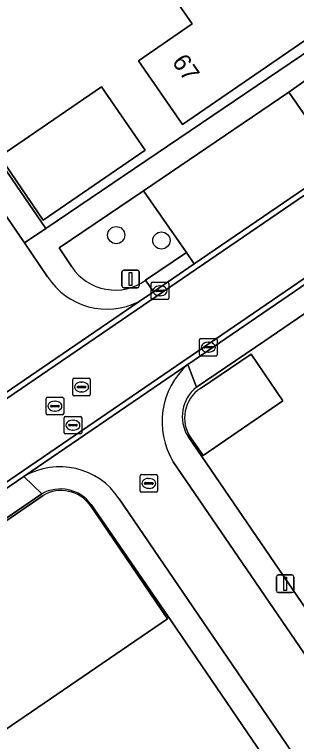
# Model space of a CAD drawing. Extents: x 155275 to 156265, y 382654 to 383635.
# Drawn here: x 155684.01 to 155700.06, y 383313.6 to 383354.97 of the extents above; entities that cross this region are included whole.
import ezdxf

# ---------------------------------------------------------------- set-up
doc = ezdxf.new("R2010")
doc.units = 0
for name, color, linetype in [('IMGEO_Boom', 7, 'Continuous'), ('IMGEO_Erf', 7, 'Continuous'), ('IMGEO_Groenvoorziening', 7, 'Continuous'), ('IMGEO_Kolk', 7, 'Continuous'), ('IMGEO_Lichtmast', 7, 'Continuous'), ('IMGEO_Pand', 7, 'Continuous'), ('IMGEO_Pand_nummerreeks', 7, 'Continuous'), ('IMGEO_Parkeervlak_open', 7, 'Continuous'), ('IMGEO_Rijbaan_lokaal_gesloten', 7, 'Continuous'), ('IMGEO_Rijbaan_lokaal_open', 7, 'Continuous'), ('IMGEO_Rioolput', 7, 'Continuous'), ('IMGEO_Voetpad_open', 7, 'Continuous')]:
    doc.layers.add(name, color=color, linetype=linetype)

msp = doc.modelspace()

# ---------------------------------------------------------------- linework, layer by layer
at = {"layer": 'IMGEO_Boom'}
for centre in [(155689.797, 383342.417), (155692.37, 383342.11)]:
    msp.add_circle(centre, 0.489, dxfattribs=at)
at = {"layer": 'IMGEO_Erf'}
for points in [[(155657.299, 383431.777), (155657.022, 383432.185), (155634.905, 383417.186), (155657.35, 383384.321), (155685.798, 383342.799), (155707.917, 383357.778), (155706.87, 383359.32)], [(155701.527, 383364.294), (155705.591, 383358.305), (155702.158, 383355.941), (155702.775, 383355.037), (155693.566, 383348.712), (155691.075, 383352.342), (155694.125, 383354.435), (155691.858, 383357.712)], [(155688.953, 383350.864), (155691.436, 383347.249), (155685.648, 383343.273), (155683.165, 383346.888)]]:
    msp.add_lwpolyline(points, close=True, dxfattribs=at)
for points in [[(155753.838, 383283.279), (155753.674, 383283.392), (155756.107, 383286.947), (155756.272, 383286.834), (155756.341, 383286.918), (155755.683, 383287.816), (155714.768, 383347.689), (155698.263, 383336.406), (155694.36, 383333.757)], [(155694.587, 383333.694), (155697.477, 383335.633), (155699.272, 383332.982), (155694.749, 383329.883)], [(155693.884, 383330.96), (155734.469, 383271.59), (155728.87, 383267.725), (155692.93, 383320.467), (155688.369, 383327.082)], [(155694.749, 383329.883), (155694.043, 383330.876)], [(155685.56, 383327.69), (155661.788, 383311.41), (155661.818, 383311.37), (155722.08, 383223.219), (155746.422, 383187.612), (155746.888, 383186.944), (155747.971, 383187.224)], [(155683.482, 383314.262), (155682.239, 383316.077), (155675.748, 383311.563), (155676.947, 383309.789), (155671.686, 383306.168), (155667.803, 383311.897), (155669.27, 383312.926), (155667.643, 383315.246), (155685.633, 383327.606)], [(155688.329, 383327.031), (155692.719, 383320.588), (155683.482, 383314.262)]]:
    msp.add_lwpolyline(points, dxfattribs=at)
for centre, radius, start, end in [((155695.67, 383332.095), 2.116, 128.2453, 212.4383), ((155695.693, 383332.019), 2.008, 123.4462, 214.7013), ((155686.626, 383325.821), 2.151, 35.8759, 119.6979), ((155686.66, 383325.814), 2.066, 36.104, 119.8168)]:
    msp.add_arc(centre, radius, start, end, dxfattribs=at)
at = {"layer": 'IMGEO_Groenvoorziening'}
msp.add_lwpolyline([(155701.519, 383351.894), (155699.624, 383350.551), (155702.029, 383347.077), (155703.937, 383348.365)], close=True, dxfattribs=at)
for points in [[(155691.357, 383344.944), (155686.548, 383341.702), (155687.272, 383340.604)], [(155691.465, 383339.856), (155693.799, 383341.42), (155691.357, 383344.944)]]:
    msp.add_lwpolyline(points, dxfattribs=at)
msp.add_arc((155689.726, 383342.235), 2.947, 213.6059, 306.1646, dxfattribs=at)
at = {"layer": 'IMGEO_Kolk'}
for p, q in [((155691.79, 383338.821), (155691.79, 383339.673)), ((155691.865, 383339.747), (155692.717, 383339.747)), ((155692.278, 383339.527), (155692.303, 383339.527)), ((155692.791, 383339.673), (155692.791, 383338.821)), ((155692.049, 383339.241), (155692.049, 383339.253)), ((155692.487, 383339.204), (155692.089, 383339.204)), ((155692.092, 383339.29), (155692.49, 383339.29)), ((155692.533, 383339.253), (155692.533, 383339.241)), ((155692.717, 383338.747), (155691.865, 383338.747)), ((155692.301, 383338.967), (155692.276, 383338.967)), ((155694.538, 383335.612), (155694.538, 383336.464)), ((155694.613, 383336.538), (155695.465, 383336.538)), ((155695.026, 383336.318), (155695.051, 383336.318)), ((155695.539, 383336.464), (155695.539, 383335.612)), ((155694.797, 383336.032), (155694.797, 383336.044)), ((155695.235, 383335.995), (155694.837, 383335.995)), ((155694.84, 383336.081), (155695.238, 383336.081)), ((155695.281, 383336.044), (155695.281, 383336.032)), ((155695.465, 383335.538), (155694.613, 383335.538)), ((155695.049, 383335.758), (155695.024, 383335.758)), ((155691.228, 383328.787), (155692.08, 383328.787)), ((155691.153, 383327.861), (155691.153, 383328.713)), ((155691.641, 383328.567), (155691.666, 383328.567)), ((155692.154, 383328.713), (155692.154, 383327.861)), ((155691.412, 383328.281), (155691.412, 383328.293)), ((155691.85, 383328.244), (155691.452, 383328.244)), ((155691.455, 383328.33), (155691.853, 383328.33)), ((155691.664, 383328.007), (155691.639, 383328.007)), ((155691.896, 383328.293), (155691.896, 383328.281)), ((155692.08, 383327.787), (155691.228, 383327.787))]:
    msp.add_line(p, q, dxfattribs=at)
for points in [[(155691.79, 383338.821), (155691.79, 383339.673)], [(155691.865, 383339.747), (155692.717, 383339.747)], [(155692.791, 383339.673), (155692.791, 383338.821)], [(155692.717, 383338.747), (155691.865, 383338.747)], [(155694.538, 383335.612), (155694.538, 383336.464)], [(155694.613, 383336.538), (155695.465, 383336.538)], [(155695.539, 383336.464), (155695.539, 383335.612)], [(155695.465, 383335.538), (155694.613, 383335.538)], [(155691.228, 383328.787), (155692.08, 383328.787)], [(155691.153, 383327.861), (155691.153, 383328.713)], [(155692.154, 383328.713), (155692.154, 383327.861)], [(155692.08, 383327.787), (155691.228, 383327.787)]]:
    msp.add_lwpolyline(points, dxfattribs=at)
for centre, radius, start, end in [((155691.867, 383339.671), 0.0765, 91.552, 178.448), ((155691.867, 383339.671), 0.0765, 91.552, 178.448), ((155692.715, 383339.671), 0.0765, 1.552, 88.448), ((155692.715, 383339.671), 0.0765, 1.552, 88.448), ((155692.089, 383339.25), 0.0403, 85.8775, 175.7526), ((155692.086, 383339.24), 0.0366, 178.938, 274.7102), ((155692.49, 383339.247), 0.043, 264.8664, 352.4533), ((155692.494, 383339.252), 0.0386, 1.7309, 96.639), ((155691.867, 383338.823), 0.0765, 181.552, 268.448), ((155691.867, 383338.823), 0.0765, 181.552, 268.448), ((155692.715, 383338.823), 0.0765, 271.552, 358.448), ((155692.715, 383338.823), 0.0765, 271.552, 358.448), ((155694.615, 383336.462), 0.0765, 91.552, 178.448), ((155694.615, 383336.462), 0.0765, 91.552, 178.448), ((155695.463, 383336.462), 0.0765, 1.552, 88.448), ((155695.463, 383336.462), 0.0765, 1.552, 88.448), ((155694.837, 383336.041), 0.0403, 85.8775, 175.7526), ((155694.834, 383336.031), 0.0366, 178.938, 274.7102), ((155695.238, 383336.038), 0.043, 264.8664, 352.4533), ((155695.242, 383336.043), 0.0386, 1.7309, 96.639), ((155694.615, 383335.614), 0.0765, 181.552, 268.448), ((155694.615, 383335.614), 0.0765, 181.552, 268.448), ((155695.463, 383335.614), 0.0765, 271.552, 358.448), ((155695.463, 383335.614), 0.0765, 271.552, 358.448), ((155691.23, 383328.711), 0.0765, 91.552, 178.448), ((155691.23, 383328.711), 0.0765, 91.552, 178.448), ((155692.078, 383328.711), 0.0765, 1.552, 88.448), ((155692.078, 383328.711), 0.0765, 1.552, 88.448), ((155691.452, 383328.29), 0.0403, 85.8775, 175.7526), ((155691.449, 383328.28), 0.0366, 178.938, 274.7102), ((155691.853, 383328.287), 0.043, 264.8664, 352.4533), ((155691.857, 383328.292), 0.0386, 1.7309, 96.639), ((155691.23, 383327.863), 0.0765, 181.552, 268.448), ((155691.23, 383327.863), 0.0765, 181.552, 268.448), ((155692.078, 383327.863), 0.0765, 271.552, 358.448), ((155692.078, 383327.863), 0.0765, 271.552, 358.448)]:
    msp.add_arc(centre, radius, start, end, dxfattribs=at)
for centre, major_axis, ratio, start_param, end_param in [((155692.277, 383339.247), (-0.387, 0.002), 0.722429, 4.712389, 7.853982), ((155692.302, 383339.247), (-0.39, 0.002), 0.717154, 1.570796, 4.712389), ((155695.025, 383336.038), (-0.387, 0.002), 0.722429, 4.712389, 7.853982), ((155695.05, 383336.038), (-0.39, 0.002), 0.717154, 1.570796, 4.712389), ((155691.64, 383328.287), (-0.387, 0.002), 0.722429, 4.712389, 7.853982), ((155691.665, 383328.287), (-0.39, 0.002), 0.717154, 1.570796, 4.712389)]:
    msp.add_ellipse(centre, major_axis=major_axis, ratio=ratio, start_param=start_param, end_param=end_param, dxfattribs=at)
at = {"layer": 'IMGEO_Lichtmast'}
for p, q in [((155690.223, 383340.423), (155691.013, 383340.423)), ((155691.013, 383340.423), (155690.223, 383340.423)), ((155690.123, 383339.523), (155690.123, 383340.323)), ((155690.123, 383340.323), (155690.123, 383339.523)), ((155691.113, 383340.323), (155691.113, 383339.523)), ((155691.113, 383339.523), (155691.113, 383340.323)), ((155691.013, 383339.423), (155690.223, 383339.423)), ((155690.223, 383339.423), (155691.013, 383339.423)), ((155699.011, 383323.076), (155699.801, 383323.076)), ((155699.801, 383323.076), (155699.011, 383323.076)), ((155698.911, 383322.176), (155698.911, 383322.976)), ((155698.911, 383322.976), (155698.911, 383322.176)), ((155699.901, 383322.976), (155699.901, 383322.176)), ((155699.901, 383322.176), (155699.901, 383322.976)), ((155699.801, 383322.076), (155699.011, 383322.076)), ((155699.011, 383322.076), (155699.801, 383322.076))]:
    msp.add_line(p, q, dxfattribs=at)
for points in [[(155690.543, 383340.298), (155690.693, 383340.298), (155690.693, 383339.548), (155690.543, 383339.548), (155690.543, 383340.298)], [(155699.331, 383322.951), (155699.481, 383322.951), (155699.481, 383322.201), (155699.331, 383322.201), (155699.331, 383322.951)]]:
    msp.add_lwpolyline(points, dxfattribs=at)
for centre, start, end in [((155690.223, 383340.323), 90, 180), ((155690.223, 383340.323), 90, 180), ((155691.013, 383340.323), 0, 90), ((155691.013, 383340.323), 360, 90), ((155690.223, 383339.523), 180, 270), ((155690.223, 383339.523), 180, 270), ((155691.013, 383339.523), 270, 0), ((155691.013, 383339.523), 270, 0), ((155699.011, 383322.976), 90, 180), ((155699.011, 383322.976), 90, 180), ((155699.801, 383322.976), 0, 90), ((155699.801, 383322.976), 360, 90), ((155699.011, 383322.176), 180, 270), ((155699.011, 383322.176), 180, 270), ((155699.801, 383322.176), 270, 0), ((155699.801, 383322.176), 270, 0)]:
    msp.add_arc(centre, 0.1, start, end, dxfattribs=at)
at = {"layer": 'IMGEO_Pand'}
for points in [[(155701.527, 383364.294), (155691.858, 383357.712), (155694.125, 383354.435), (155691.075, 383352.342), (155693.566, 383348.712), (155702.775, 383355.037), (155702.158, 383355.941), (155705.591, 383358.305)], [(155685.648, 383343.273), (155691.436, 383347.249), (155688.953, 383350.864), (155683.165, 383346.888)]]:
    msp.add_lwpolyline(points, close=True, dxfattribs=at)
for points in [[(155699.272, 383332.982), (155697.477, 383335.633), (155694.587, 383333.694)], [(155694.043, 383330.876), (155694.749, 383329.883), (155699.272, 383332.982)], [(155685.633, 383327.606), (155667.643, 383315.246), (155669.27, 383312.926), (155667.803, 383311.897), (155671.686, 383306.168), (155676.947, 383309.789), (155675.748, 383311.563), (155682.239, 383316.077), (155683.482, 383314.262), (155692.719, 383320.588), (155688.329, 383327.031)]]:
    msp.add_lwpolyline(points, dxfattribs=at)
for centre, radius, start, end in [((155695.693, 383332.019), 2.008, 123.4462, 214.7013), ((155686.66, 383325.814), 2.066, 36.104, 119.8168)]:
    msp.add_arc(centre, radius, start, end, dxfattribs=at)
at = {"layer": 'IMGEO_Parkeervlak_open'}
msp.add_lwpolyline([(155702.484, 383346.42), (155702.029, 383347.077), (155699.624, 383350.551), (155691.357, 383344.944), (155693.799, 383341.42), (155694.239, 383340.786)], close=True, dxfattribs=at)
at = {"layer": 'IMGEO_Rijbaan_lokaal_gesloten'}
msp.add_lwpolyline([(155729.169, 383364.646), (155725.003, 383361.806), (155722.109, 383359.832), (155720.939, 383359.034), (155720.795, 383358.936), (155712.721, 383353.417), (155711.461, 383352.556), (155708.502, 383350.534), (155704.381, 383347.717), (155702.484, 383346.42), (155694.239, 383340.786), (155691.911, 383339.195), (155691.095, 383338.637), (155682.011, 383332.429), (155681.289, 383331.935), (155676.837, 383328.892), (155670.662, 383324.672), (155666.533, 383321.85), (155664.45, 383320.426), (155661.244, 383318.235), (155661.404, 383317.986), (155721.169, 383358.828), (155779.897, 383398.895)], dxfattribs=at)
msp.add_lwpolyline([(155753.96, 383376.139), (155759.005, 383379.588), (155782.291, 383395.421), (155782.106, 383395.69), (155715.377, 383350.126), (155663.845, 383314.887), (155664.009, 383314.637), (155684.541, 383328.678), (155693.872, 383335.059), (155715.33, 383349.733), (155745.158, 383370.123)], close=True, dxfattribs=at)
at = {"layer": 'IMGEO_Rijbaan_lokaal_open'}
for points in [[(155685.887, 383340.048), (155684.569, 383341.975), (155633.677, 383416.365)], [(155782.106, 383395.69), (155779.897, 383398.895), (155721.169, 383358.828), (155661.404, 383317.986), (155661.244, 383318.235), (155660.115, 383317.515)], [(155662.689, 383313.737), (155664.009, 383314.637), (155663.845, 383314.887), (155715.377, 383350.126), (155782.106, 383395.69)], [(155682.011, 383332.429), (155691.095, 383338.637)], [(155693.872, 383335.059), (155684.541, 383328.678)], [(155689.962, 383327.416), (155729.272, 383269.785), (155732.407, 383271.977), (155693.039, 383329.522)]]:
    msp.add_lwpolyline(points, dxfattribs=at)
for centre, radius, start, end in [((155689.276, 383342.241), 4.037, 212.9045, 296.7771), ((155696.778, 383331.791), 4.373, 131.6399, 211.249), ((155686.587, 383325.192), 4.042, 33.382, 120.4081)]:
    msp.add_arc(centre, radius, start, end, dxfattribs=at)
at = {"layer": 'IMGEO_Rioolput'}
for p, q in [((155687.323, 383333.345), (155687.323, 383334.197)), ((155687.398, 383334.271), (155688.25, 383334.271)), ((155688.324, 383334.197), (155688.324, 383333.345)), ((155687.582, 383333.765), (155687.582, 383333.777)), ((155687.625, 383333.814), (155688.023, 383333.814)), ((155687.811, 383334.051), (155687.836, 383334.051)), ((155688.066, 383333.777), (155688.066, 383333.765)), ((155688.02, 383333.728), (155687.622, 383333.728)), ((155687.834, 383333.491), (155687.809, 383333.491)), ((155685.809, 383332.261), (155685.809, 383333.113)), ((155685.884, 383333.187), (155686.736, 383333.187)), ((155686.297, 383332.967), (155686.322, 383332.967)), ((155686.81, 383333.113), (155686.81, 383332.261)), ((155688.25, 383333.271), (155687.398, 383333.271)), ((155686.068, 383332.681), (155686.068, 383332.693)), ((155686.506, 383332.644), (155686.108, 383332.644)), ((155686.111, 383332.73), (155686.509, 383332.73)), ((155686.552, 383332.693), (155686.552, 383332.681)), ((155686.736, 383332.187), (155685.884, 383332.187)), ((155686.32, 383332.407), (155686.295, 383332.407)), ((155686.908, 383332.1), (155687.76, 383332.1)), ((155686.833, 383331.174), (155686.833, 383332.026)), ((155687.321, 383331.88), (155687.346, 383331.88)), ((155687.834, 383332.026), (155687.834, 383331.174)), ((155687.092, 383331.594), (155687.092, 383331.606)), ((155687.53, 383331.557), (155687.132, 383331.557)), ((155687.135, 383331.643), (155687.533, 383331.643)), ((155687.344, 383331.32), (155687.319, 383331.32)), ((155687.576, 383331.606), (155687.576, 383331.594)), ((155687.76, 383331.1), (155686.908, 383331.1))]:
    msp.add_line(p, q, dxfattribs=at)
for points in [[(155687.323, 383333.345), (155687.323, 383334.197)], [(155687.398, 383334.271), (155688.25, 383334.271)], [(155688.324, 383334.197), (155688.324, 383333.345)], [(155685.809, 383332.261), (155685.809, 383333.113)], [(155685.884, 383333.187), (155686.736, 383333.187)], [(155686.81, 383333.113), (155686.81, 383332.261)], [(155688.25, 383333.271), (155687.398, 383333.271)], [(155686.736, 383332.187), (155685.884, 383332.187)], [(155686.908, 383332.1), (155687.76, 383332.1)], [(155686.833, 383331.174), (155686.833, 383332.026)], [(155687.834, 383332.026), (155687.834, 383331.174)], [(155687.76, 383331.1), (155686.908, 383331.1)]]:
    msp.add_lwpolyline(points, dxfattribs=at)
for centre, radius, start, end in [((155687.4, 383334.195), 0.0765, 91.552, 178.448), ((155687.4, 383334.195), 0.0765, 91.552, 178.448), ((155688.248, 383334.195), 0.0765, 1.552, 88.448), ((155688.248, 383334.195), 0.0765, 1.552, 88.448), ((155687.622, 383333.774), 0.0403, 85.8775, 175.7526), ((155687.619, 383333.764), 0.0366, 178.938, 274.7102), ((155688.023, 383333.771), 0.043, 264.8664, 352.4533), ((155688.027, 383333.776), 0.0386, 1.7309, 96.639), ((155687.4, 383333.347), 0.0765, 181.552, 268.448), ((155687.4, 383333.347), 0.0765, 181.552, 268.448), ((155688.248, 383333.347), 0.0765, 271.552, 358.448), ((155688.248, 383333.347), 0.0765, 271.552, 358.448), ((155685.886, 383333.111), 0.0765, 91.552, 178.448), ((155685.886, 383333.111), 0.0765, 91.552, 178.448), ((155686.734, 383333.111), 0.0765, 1.552, 88.448), ((155686.734, 383333.111), 0.0765, 1.552, 88.448), ((155686.108, 383332.69), 0.0403, 85.8775, 175.7526), ((155686.105, 383332.68), 0.0366, 178.938, 274.7102), ((155686.509, 383332.687), 0.043, 264.8664, 352.4533), ((155686.513, 383332.692), 0.0386, 1.7309, 96.639), ((155685.886, 383332.263), 0.0765, 181.552, 268.448), ((155685.886, 383332.263), 0.0765, 181.552, 268.448), ((155686.734, 383332.263), 0.0765, 271.552, 358.448), ((155686.734, 383332.263), 0.0765, 271.552, 358.448), ((155686.91, 383332.024), 0.0765, 91.552, 178.448), ((155686.91, 383332.024), 0.0765, 91.552, 178.448), ((155687.758, 383332.024), 0.0765, 1.552, 88.448), ((155687.758, 383332.024), 0.0765, 1.552, 88.448), ((155687.132, 383331.603), 0.0403, 85.8775, 175.7526), ((155687.129, 383331.593), 0.0366, 178.938, 274.7102), ((155687.533, 383331.6), 0.043, 264.8664, 352.4533), ((155687.537, 383331.605), 0.0386, 1.7309, 96.639), ((155686.91, 383331.176), 0.0765, 181.552, 268.448), ((155686.91, 383331.176), 0.0765, 181.552, 268.448), ((155687.758, 383331.176), 0.0765, 271.552, 358.448), ((155687.758, 383331.176), 0.0765, 271.552, 358.448)]:
    msp.add_arc(centre, radius, start, end, dxfattribs=at)
for centre, major_axis, ratio, start_param, end_param in [((155687.81, 383333.771), (-0.387, 0.002), 0.722429, 4.712389, 7.853982), ((155687.835, 383333.771), (-0.39, 0.002), 0.717154, 1.570796, 4.712389), ((155686.296, 383332.687), (-0.387, 0.002), 0.722429, 4.712389, 7.853982), ((155686.321, 383332.687), (-0.39, 0.002), 0.717154, 1.570796, 4.712389), ((155687.32, 383331.6), (-0.387, 0.002), 0.722429, 4.712389, 7.853982), ((155687.345, 383331.6), (-0.39, 0.002), 0.717154, 1.570796, 4.712389)]:
    msp.add_ellipse(centre, major_axis=major_axis, ratio=ratio, start_param=start_param, end_param=end_param, dxfattribs=at)
at = {"layer": 'IMGEO_Voetpad_open'}
for points in [[(155634.905, 383417.186), (155633.677, 383416.365), (155684.569, 383341.975), (155685.798, 383342.799), (155657.35, 383384.321)], [(155714.768, 383347.689), (155716.015, 383348.542), (155720.581, 383351.663), (155724.137, 383354.089), (155725.382, 383354.939), (155745.715, 383368.811), (155745.158, 383370.123), (155715.33, 383349.733), (155693.872, 383335.059), (155694.36, 383333.757), (155698.263, 383336.406)], [(155694.239, 383340.786), (155693.799, 383341.42), (155691.465, 383339.856), (155691.911, 383339.195)]]:
    msp.add_lwpolyline(points, close=True, dxfattribs=at)
for points in [[(155686.548, 383341.702), (155691.357, 383344.944), (155699.624, 383350.551), (155701.519, 383351.894), (155705.676, 383354.691), (155708.636, 383356.718), (155707.917, 383357.778), (155685.798, 383342.799), (155684.569, 383341.975), (155685.887, 383340.048)], [(155687.272, 383340.604), (155686.548, 383341.702)], [(155691.095, 383338.637), (155691.911, 383339.195), (155691.465, 383339.856)], [(155694.36, 383333.757), (155693.872, 383335.059)], [(155688.369, 383327.082), (155692.93, 383320.467), (155728.87, 383267.725), (155734.469, 383271.59), (155693.884, 383330.96)], [(155693.039, 383329.522), (155732.407, 383271.977), (155729.272, 383269.785), (155689.962, 383327.416)], [(155685.56, 383327.69), (155684.541, 383328.678), (155664.009, 383314.637), (155662.689, 383313.737)], [(155684.541, 383328.678), (155685.56, 383327.69)], [(155661.168, 383312.166), (155661.788, 383311.41), (155685.56, 383327.69)]]:
    msp.add_lwpolyline(points, dxfattribs=at)
for centre, radius, start, end in [((155689.726, 383342.235), 2.947, 213.6059, 306.1646), ((155689.276, 383342.241), 4.037, 212.9045, 296.7771), ((155696.778, 383331.791), 4.373, 131.6399, 211.249), ((155695.67, 383332.095), 2.116, 128.2453, 212.4383), ((155686.587, 383325.192), 4.042, 33.382, 120.4081), ((155686.626, 383325.821), 2.151, 35.8759, 119.6979)]:
    msp.add_arc(centre, radius, start, end, dxfattribs=at)

# ---------------------------------------------------------------- texts
at = {"layer": 'IMGEO_Pand_nummerreeks'}
msp.add_text('67', height=1, rotation=304.2627, dxfattribs=at).set_placement((155692.94, 383352.28))

doc.saveas('drawing.dxf')
